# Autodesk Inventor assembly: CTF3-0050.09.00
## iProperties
Shininess: 64.0
Length Units: 11269
Angle Units: 11279
Time Units: 11290
Mass Units: 11283
Length Display Precision: 3
Angle Display Precision: 2
Compacted: True
Created: 2003-11
Part Number: CTF3-0050.09.00
Document SubType Name: Assembly
Designer: Lollo
Density: 0.0
Volumn: 0.0
Area: 0.0
PropertySet Name: Model Information
Control State: 0
Master: False
Checked Out: False
Author: Lollo
